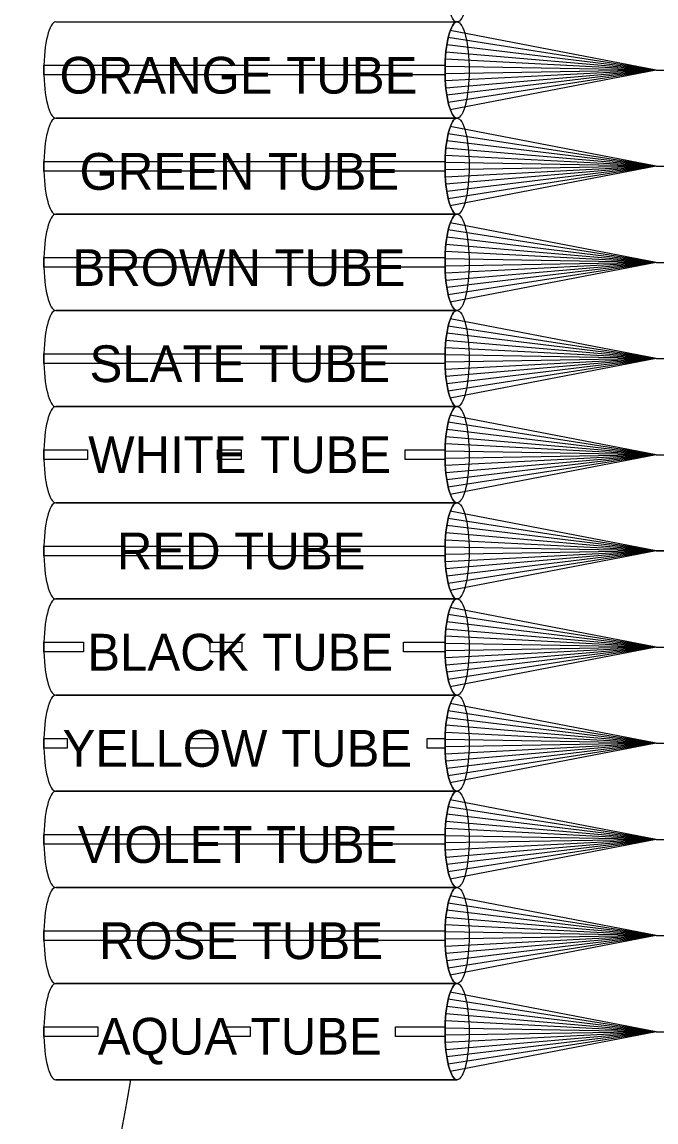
# Model space of a CAD drawing. Extents: x 1805893 to 1833564, y 708898 to 716199.
# Drawn here: x 1831642.7 to 1831682.2, y 715850.1 to 715918.7 of the extents above; entities that cross this region are included whole.
import ezdxf

# ---------------------------------------------------------------- set-up
doc = ezdxf.new("R2010")
doc.units = 0
doc.layers.add('SH_Data', color=7, linetype='Continuous')

msp = doc.modelspace()

# ---------------------------------------------------------------- linework, layer by layer
at = {"layer": 'SH_Data'}
for p, q in [((1831644.773, 715918.733), (1831669.823, 715918.733)), ((1831682.244, 715915.733), (1831669.27, 715917.758)), ((1831682.244, 715915.733), (1831669.4, 715918.208)), ((1831682.244, 715915.733), (1831669.185, 715917.308)), ((1831682.244, 715915.733), (1831669.093, 715916.408)), ((1831682.244, 715915.733), (1831669.128, 715916.858)), ((1831682.244, 715915.733), (1831669.076, 715915.958)), ((1831682.244, 715915.733), (1831669.076, 715915.508)), ((1831682.244, 715915.733), (1831669.093, 715915.058)), ((1831682.244, 715915.733), (1831669.128, 715914.608)), ((1831682.244, 715915.733), (1831669.185, 715914.158)), ((1831682.244, 715915.733), (1831669.27, 715913.708)), ((1831682.244, 715915.733), (1831669.4, 715913.258)), ((1831682.244, 715915.733), (1831734.316, 715915.733)), ((1831682.244, 715915.733), (1831734.316, 715915.733)), ((1831644.773, 715912.733), (1831669.823, 715912.733)), ((1831669.823, 715912.733), (1831644.773, 715912.733)), ((1831682.244, 715909.733), (1831669.4, 715912.208)), ((1831682.244, 715909.733), (1831669.27, 715911.758)), ((1831682.244, 715909.733), (1831669.128, 715910.858)), ((1831682.244, 715909.733), (1831669.185, 715911.308)), ((1831682.244, 715909.733), (1831669.093, 715910.408)), ((1831682.244, 715909.733), (1831669.076, 715909.958)), ((1831682.244, 715909.733), (1831669.076, 715909.508)), ((1831682.244, 715909.733), (1831669.093, 715909.058)), ((1831682.244, 715909.733), (1831669.128, 715908.608)), ((1831682.244, 715909.733), (1831669.185, 715908.158)), ((1831682.244, 715909.733), (1831669.27, 715907.708)), ((1831682.244, 715909.733), (1831669.4, 715907.258)), ((1831682.244, 715909.733), (1831734.316, 715909.733)), ((1831682.244, 715909.733), (1831734.316, 715909.733)), ((1831669.823, 715906.733), (1831644.773, 715906.733)), ((1831644.773, 715906.733), (1831669.823, 715906.733)), ((1831682.244, 715903.733), (1831669.4, 715906.208)), ((1831682.244, 715903.733), (1831669.185, 715905.308)), ((1831682.244, 715903.733), (1831669.27, 715905.758)), ((1831682.244, 715903.733), (1831669.128, 715904.858)), ((1831682.244, 715903.733), (1831669.076, 715903.958)), ((1831682.244, 715903.733), (1831669.093, 715904.408)), ((1831682.244, 715903.733), (1831669.076, 715903.508)), ((1831682.244, 715903.733), (1831669.093, 715903.058)), ((1831682.244, 715903.733), (1831669.128, 715902.608)), ((1831682.244, 715903.733), (1831669.185, 715902.158)), ((1831682.244, 715903.733), (1831669.27, 715901.708)), ((1831682.244, 715903.733), (1831669.4, 715901.258)), ((1831682.244, 715903.733), (1831734.316, 715903.733)), ((1831682.244, 715903.733), (1831734.316, 715903.733)), ((1831669.823, 715900.733), (1831644.773, 715900.733)), ((1831644.773, 715900.733), (1831669.823, 715900.733)), ((1831682.244, 715897.733), (1831669.4, 715900.208)), ((1831682.244, 715897.733), (1831669.185, 715899.308)), ((1831682.244, 715897.733), (1831669.27, 715899.758)), ((1831682.244, 715897.733), (1831669.093, 715898.408)), ((1831682.244, 715897.733), (1831669.128, 715898.858)), ((1831682.244, 715897.733), (1831669.076, 715897.958)), ((1831682.244, 715897.733), (1831669.076, 715897.508)), ((1831682.244, 715897.733), (1831669.093, 715897.058)), ((1831682.244, 715897.733), (1831669.128, 715896.608)), ((1831682.244, 715897.733), (1831669.185, 715896.158)), ((1831682.244, 715897.733), (1831669.27, 715895.708)), ((1831682.244, 715897.733), (1831669.4, 715895.258)), ((1831682.244, 715897.733), (1831734.316, 715897.733)), ((1831682.244, 715897.733), (1831734.316, 715897.733)), ((1831669.823, 715894.733), (1831644.773, 715894.733)), ((1831644.773, 715894.733), (1831669.823, 715894.733)), ((1831682.244, 715891.733), (1831669.27, 715893.758)), ((1831682.244, 715891.733), (1831669.4, 715894.208)), ((1831682.244, 715891.733), (1831669.185, 715893.308)), ((1831682.244, 715891.733), (1831669.093, 715892.408)), ((1831682.244, 715891.733), (1831669.128, 715892.858)), ((1831682.244, 715891.733), (1831669.076, 715891.958)), ((1831682.244, 715891.733), (1831669.076, 715891.508)), ((1831682.244, 715891.733), (1831669.093, 715891.058)), ((1831682.244, 715891.733), (1831669.128, 715890.608)), ((1831682.244, 715891.733), (1831669.185, 715890.158)), ((1831682.244, 715891.733), (1831669.27, 715889.708)), ((1831682.244, 715891.733), (1831669.4, 715889.258)), ((1831682.244, 715891.733), (1831734.316, 715891.733)), ((1831669.823, 715888.733), (1831644.773, 715888.733)), ((1831644.773, 715888.733), (1831669.823, 715888.733)), ((1831682.244, 715885.733), (1831669.4, 715888.208)), ((1831682.244, 715885.733), (1831669.27, 715887.758)), ((1831682.244, 715885.733), (1831669.128, 715886.858)), ((1831682.244, 715885.733), (1831669.185, 715887.308)), ((1831682.244, 715885.733), (1831669.093, 715886.408)), ((1831682.244, 715885.733), (1831669.076, 715885.958)), ((1831682.244, 715885.733), (1831669.076, 715885.508)), ((1831682.244, 715885.733), (1831669.093, 715885.058)), ((1831682.244, 715885.733), (1831669.128, 715884.608)), ((1831682.244, 715885.733), (1831669.185, 715884.158)), ((1831682.244, 715885.733), (1831669.27, 715883.708)), ((1831682.244, 715885.733), (1831669.4, 715883.258)), ((1831734.316, 715885.733), (1831682.244, 715885.733)), ((1831682.244, 715885.733), (1831734.316, 715885.733)), ((1831669.823, 715882.733), (1831644.773, 715882.733)), ((1831644.773, 715882.733), (1831669.823, 715882.733)), ((1831682.244, 715879.733), (1831669.4, 715882.208)), ((1831682.244, 715879.733), (1831669.185, 715881.308)), ((1831682.244, 715879.733), (1831669.27, 715881.758)), ((1831682.244, 715879.733), (1831669.128, 715880.858)), ((1831682.244, 715879.733), (1831669.076, 715879.958)), ((1831682.244, 715879.733), (1831669.093, 715880.408)), ((1831682.244, 715879.733), (1831669.076, 715879.508)), ((1831682.244, 715879.733), (1831669.093, 715879.058)), ((1831682.244, 715879.733), (1831669.128, 715878.608)), ((1831682.244, 715879.733), (1831669.185, 715878.158)), ((1831682.244, 715879.733), (1831669.27, 715877.708)), ((1831682.244, 715879.733), (1831669.4, 715877.258)), ((1831682.244, 715879.733), (1831734.316, 715879.733)), ((1831682.244, 715879.733), (1831734.316, 715879.733)), ((1831644.773, 715876.733), (1831669.823, 715876.733)), ((1831669.823, 715876.733), (1831644.773, 715876.733)), ((1831682.244, 715873.733), (1831669.27, 715875.758)), ((1831682.244, 715873.733), (1831669.4, 715876.208)), ((1831682.244, 715873.733), (1831669.185, 715875.308)), ((1831682.244, 715873.733), (1831669.093, 715874.408)), ((1831682.244, 715873.733), (1831669.128, 715874.858)), ((1831682.244, 715873.733), (1831669.076, 715873.958)), ((1831682.244, 715873.733), (1831669.076, 715873.508)), ((1831682.244, 715873.733), (1831669.093, 715873.058)), ((1831682.244, 715873.733), (1831669.128, 715872.608)), ((1831682.244, 715873.733), (1831669.185, 715872.158)), ((1831682.244, 715873.733), (1831669.27, 715871.708)), ((1831682.244, 715873.733), (1831669.4, 715871.258)), ((1831682.244, 715873.733), (1831734.316, 715873.733)), ((1831682.244, 715873.733), (1831734.316, 715873.733)), ((1831669.823, 715870.733), (1831644.773, 715870.733)), ((1831644.773, 715870.733), (1831669.823, 715870.733)), ((1831682.244, 715867.733), (1831669.27, 715869.758)), ((1831682.244, 715867.733), (1831669.4, 715870.208)), ((1831682.244, 715867.733), (1831669.185, 715869.308)), ((1831682.244, 715867.733), (1831669.093, 715868.408)), ((1831682.244, 715867.733), (1831669.128, 715868.858)), ((1831682.244, 715867.733), (1831669.076, 715867.958)), ((1831682.244, 715867.733), (1831669.076, 715867.508)), ((1831682.244, 715867.733), (1831669.093, 715867.058)), ((1831682.244, 715867.733), (1831669.128, 715866.608)), ((1831682.244, 715867.733), (1831669.185, 715866.158)), ((1831682.244, 715867.733), (1831669.27, 715865.708)), ((1831682.244, 715867.733), (1831669.4, 715865.258)), ((1831682.244, 715867.733), (1831734.316, 715867.733)), ((1831682.244, 715867.733), (1831734.316, 715867.733)), ((1831669.823, 715864.733), (1831644.773, 715864.733)), ((1831644.773, 715864.733), (1831669.823, 715864.733)), ((1831682.244, 715861.733), (1831669.4, 715864.208)), ((1831682.244, 715861.733), (1831669.27, 715863.758)), ((1831682.244, 715861.733), (1831669.128, 715862.858)), ((1831682.244, 715861.733), (1831669.185, 715863.308)), ((1831682.244, 715861.733), (1831669.093, 715862.408)), ((1831682.244, 715861.733), (1831669.076, 715861.958)), ((1831682.244, 715861.733), (1831669.076, 715861.508)), ((1831682.244, 715861.733), (1831669.093, 715861.058)), ((1831682.244, 715861.733), (1831669.128, 715860.608)), ((1831682.244, 715861.733), (1831669.185, 715860.158)), ((1831682.244, 715861.733), (1831669.27, 715859.708)), ((1831682.244, 715861.733), (1831669.4, 715859.258)), ((1831682.244, 715861.733), (1831734.316, 715861.733)), ((1831682.244, 715861.733), (1831734.316, 715861.733)), ((1831669.823, 715858.733), (1831644.773, 715858.733)), ((1831644.773, 715858.733), (1831669.823, 715858.733)), ((1831682.244, 715855.733), (1831669.4, 715858.208)), ((1831682.244, 715855.733), (1831669.185, 715857.308)), ((1831682.244, 715855.733), (1831669.27, 715857.758)), ((1831682.244, 715855.733), (1831669.128, 715856.858)), ((1831682.244, 715855.733), (1831669.076, 715855.958)), ((1831682.244, 715855.733), (1831669.093, 715856.408)), ((1831682.244, 715855.733), (1831669.076, 715855.508)), ((1831682.244, 715855.733), (1831669.093, 715855.058)), ((1831682.244, 715855.733), (1831669.128, 715854.608)), ((1831682.244, 715855.733), (1831669.185, 715854.158)), ((1831682.244, 715855.733), (1831669.27, 715853.708)), ((1831682.244, 715855.733), (1831669.4, 715853.258)), ((1831682.244, 715855.733), (1831734.316, 715855.733)), ((1831669.823, 715852.733), (1831644.773, 715852.733)), ((1831644.773, 715852.733), (1831669.823, 715852.733)), ((1831669.823, 715852.733), (1831649.465, 715852.733))]:
    msp.add_line(p, q, dxfattribs=at)
for points in [[(1831644.027, 715916.033), (1831669.075, 715916.033), (1831669.075, 715915.433), (1831644.027, 715915.433)], [(1831644.027, 715910.033), (1831669.075, 715910.033), (1831669.075, 715909.433), (1831644.027, 715909.433)], [(1831644.027, 715904.033), (1831669.075, 715904.033), (1831669.075, 715903.433), (1831644.027, 715903.433)], [(1831644.027, 715898.033), (1831669.075, 715898.033), (1831669.075, 715897.433), (1831644.027, 715897.433)], [(1831644.027, 715892.033), (1831646.753, 715892.033), (1831646.753, 715891.433), (1831644.027, 715891.433)], [(1831654.859, 715892.033), (1831656.343, 715892.033), (1831656.343, 715891.433), (1831654.859, 715891.433)], [(1831666.59, 715892.033), (1831669.077, 715892.033), (1831669.077, 715891.433), (1831666.59, 715891.433)], [(1831644.027, 715886.033), (1831669.075, 715886.033), (1831669.075, 715885.433), (1831644.027, 715885.433)], [(1831644.027, 715880.033), (1831646.504, 715880.033), (1831646.504, 715879.433), (1831644.027, 715879.433)], [(1831654.404, 715880.033), (1831656.376, 715880.033), (1831656.376, 715879.433), (1831654.404, 715879.433)], [(1831666.469, 715880.033), (1831669.077, 715880.033), (1831669.077, 715879.433), (1831666.469, 715879.433)], [(1831644.027, 715874.033), (1831645.491, 715874.033), (1831645.491, 715873.433), (1831644.027, 715873.433)], [(1831652.991, 715874.033), (1831654.711, 715874.033), (1831654.711, 715873.433), (1831652.991, 715873.433)], [(1831667.949, 715874.033), (1831669.077, 715874.033), (1831669.077, 715873.433), (1831667.949, 715873.433)], [(1831644.027, 715868.033), (1831669.075, 715868.033), (1831669.075, 715867.433), (1831644.027, 715867.433)], [(1831644.027, 715862.033), (1831669.075, 715862.033), (1831669.075, 715861.433), (1831644.027, 715861.433)], [(1831644.027, 715856.033), (1831647.395, 715856.033), (1831647.395, 715855.433), (1831644.027, 715855.433)], [(1831655.39, 715856.033), (1831656.908, 715856.033), (1831656.908, 715855.433), (1831655.39, 715855.433)], [(1831665.974, 715856.033), (1831669.077, 715856.033), (1831669.077, 715855.433), (1831665.974, 715855.433)]]:
    msp.add_lwpolyline(points, close=True, dxfattribs=at)
for centre, major_axis, ratio, start_param, end_param in [((1831644.17, 715924.733), (0, -86.094), 0.112175, 2.561295, 6.863483), ((1831644.17, 715924.733), (0, -86.094), 0.112175, 2.561295, 6.863483), ((1831644.773, 715915.733), (0, -3), 0.25, 3.141593, 6.283185), ((1831644.773, 715915.733), (0, -3), 0.25, 3.141593, 6.283185), ((1831669.823, 715915.733), (0, -3), 0.25, 3.141593, 6.283185), ((1831644.773, 715909.733), (0, -3), 0.25, 3.141593, 6.283185), ((1831644.773, 715909.733), (0, -3), 0.25, 3.141593, 6.283185), ((1831669.823, 715909.733), (0, -3), 0.25, 3.141593, 6.283185), ((1831644.773, 715903.733), (0, -3), 0.25, 3.141593, 6.283185), ((1831644.773, 715903.733), (0, -3), 0.25, 3.141593, 6.283185), ((1831669.823, 715903.733), (0, -3), 0.25, 3.141593, 6.283185), ((1831644.773, 715897.733), (0, -3), 0.25, 3.141593, 6.283185), ((1831644.773, 715897.733), (0, -3), 0.25, 3.141593, 6.283185), ((1831669.823, 715897.733), (0, -3), 0.25, 3.141593, 6.283185), ((1831644.773, 715891.733), (0, -3), 0.25, 3.141593, 6.283185), ((1831644.773, 715891.733), (0, -3), 0.25, 3.141593, 6.283185), ((1831669.823, 715891.733), (0, -3), 0.25, 3.141593, 6.283185), ((1831644.773, 715885.733), (0, -3), 0.25, 3.141593, 6.283185), ((1831644.773, 715885.733), (0, -3), 0.25, 3.141593, 6.283185), ((1831669.823, 715885.733), (0, -3), 0.25, 3.141593, 6.283185), ((1831644.773, 715879.733), (0, -3), 0.25, 3.141593, 6.283185), ((1831644.773, 715879.733), (0, -3), 0.25, 3.141593, 6.283185), ((1831669.823, 715879.733), (0, -3), 0.25, 3.141593, 6.283185), ((1831644.773, 715873.733), (0, -3), 0.25, 3.141593, 6.283185), ((1831644.773, 715873.733), (0, -3), 0.25, 3.141593, 6.283185), ((1831669.823, 715873.733), (0, -3), 0.25, 3.141593, 6.283185), ((1831644.773, 715867.733), (0, -3), 0.25, 3.141593, 6.283185), ((1831644.773, 715867.733), (0, -3), 0.25, 3.141593, 6.283185), ((1831669.823, 715867.733), (0, -3), 0.25, 3.141593, 6.283185), ((1831644.773, 715861.733), (0, -3), 0.25, 3.141593, 6.283185), ((1831644.773, 715861.733), (0, -3), 0.25, 3.141593, 6.283185), ((1831669.823, 715861.733), (0, -3), 0.25, 3.141593, 6.283185), ((1831644.773, 715855.733), (0, -3), 0.25, 3.141593, 6.283185), ((1831644.773, 715855.733), (0, -3), 0.25, 3.141593, 6.283185), ((1831669.823, 715855.733), (0, -3), 0.25, 3.141593, 6.283185)]:
    msp.add_ellipse(centre, major_axis=major_axis, ratio=ratio, start_param=start_param, end_param=end_param, dxfattribs=at)
for centre in [(1831669.823, 715921.733), (1831669.823, 715915.733), (1831669.823, 715909.733), (1831669.823, 715903.733), (1831669.823, 715897.733), (1831669.823, 715891.733), (1831669.823, 715885.733), (1831669.823, 715879.733), (1831669.823, 715873.733), (1831669.823, 715867.733), (1831669.823, 715861.733), (1831669.823, 715855.733)]:
    msp.add_ellipse(centre, major_axis=(0, -3), ratio=0.25, dxfattribs=at)

# ---------------------------------------------------------------- texts
for s, height, p in [('ORANGE TUBE', 2.29468, (1831645.008, 715914.264)), ('GREEN TUBE', 2.2947, (1831646.255, 715908.264)), ('BROWN TUBE', 2.2947, (1831645.811, 715902.264)), ('SLATE TUBE', 2.2947, (1831646.877, 715896.264)), ('WHITE TUBE', 2.2947, (1831646.792, 715890.585)), ('RED TUBE', 2.2947, (1831648.58, 715884.585)), ('BLACK TUBE', 2.2947, (1831646.738, 715878.264)), ('YELLOW TUBE', 2.29468, (1831645.194, 715872.264)), ('VIOLET TUBE', 2.29468, (1831646.144, 715866.264)), ('ROSE TUBE', 2.2947, (1831647.467, 715860.264)), ('AQUA TUBE', 2.2947, (1831647.391, 715854.304))]:
    msp.add_text(s, height=height, dxfattribs=at).set_placement(p)

doc.saveas('drawing.dxf')
